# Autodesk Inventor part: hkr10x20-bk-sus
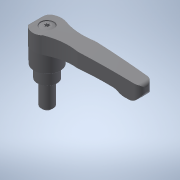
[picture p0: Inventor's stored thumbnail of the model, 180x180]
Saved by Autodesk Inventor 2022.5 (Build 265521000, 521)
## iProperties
Created: 2017-09
Part Number: hkr10x20-bk-sus
Material: 一般
Document SubType Name: Modeling
Designer: imaocorp
Density: 1 g/cm^3
Appearance: 既定
Author: imaocorp
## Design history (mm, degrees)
node "hkr10x20-bk-sus.x_t1"
node "hkr10x20-bk-sus"
node "Base1"
